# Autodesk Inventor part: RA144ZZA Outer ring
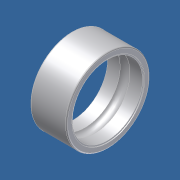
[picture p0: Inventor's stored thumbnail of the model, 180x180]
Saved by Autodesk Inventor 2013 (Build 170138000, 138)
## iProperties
Category: PARTsolutions
Created: 2011-07
Part Number: RA144ZZA Outer ring
Catalog Web Link: www.cadenas.de
Description: Six types or - Inch system sizes
Document SubType Name: Modeling
Designer: PARTsolutions
Density: 1 g/cm^3
Material: Générique
NB: RA144ZZA Outer ring
NN: Six types or
NT: Inch system sizes
NBSYN: RA144ZZA Outer ring
LINA: RA144ZZA Outer ring
SD: 3.175
D: 6.350
B: 2.380
B1: 2.779
D1: 7.52
D2: 7.52
C1: 0.58
C2: 0.79
R: 0.08
ORDER: RA144ZZA
CR: 284
COR: 96
CRF: 29
CORF: 10
LSG: 59000
LSO: 70000
MASS: 0.27
ORDER1: R144
WSS: RA144ZA
WDS: RA144ZZA
UTWF: FLR144
FORSS: FLRA144ZA
FORDS: FLRA144ZZA
DA1: 3.9
DA2: 4
DA: 5.5
RAS: 0.08
MASS1: 0.33
VERS: 3
X: 1.587
N: 9
O: 14.954
RB: 0.470
KT: DUMMY
SUPPLIER: NTN
ARTICLENO: RA144ZZA Outer ring
BOMINFO: RA144ZZA Outer ring
CREATOR: CADENAS GmbH
PSOL_IDENT_0: {\\10.0.0.251\ps_data\23d-libs\ntn\ball_roller_bearings\miniature_extra_small_bb\inch_system_sizes\i
PSOL_IDENT_1: ss_or.prj},189 {VTYP=3D},{NB=RA144ZZA Outer ring},{LINA=RA144ZZA Outer ring},{NN=Six types or},{DATE
PSOL_IDENT_2: =11.12.2007 08:48:22},{GEOMDATE=08.02.2007 08:30:00},{VERSION=},{LINEID=16080},{LINESUBID=-1},{WBVAR
PSOL_IDENT_3: =}  {NB=RA144ZZA Outer ring},{LINA=RA144ZZA Outer ring},{KT=DUMMY},{IDNR=},{SD=3.175},{D=6.350},{B=2
PSOL_IDENT_4: .380},{B1=2.779},{D1=7.52},{D2=7.52},{C1=0.58},{C2=0.79},{R=0.08},{ORDER=RA144ZZA},{CR=284},{COR=96}
PSOL_IDENT_5: ,{CRF=29},{CORF=10},{LSG=59000},{LSO=70000},{MASS=0.27},{ORDER1=R144},{WSS=RA144ZA},{WDS=RA144ZZA},{
PSOL_IDENT_6: UTWF=FLR144},{FORSS=FLRA144ZA},{FORDS=FLRA144ZZA},{DA1=3.9},{DA2=4},{DA=5.5},{RAS=0.08},{MASS1=0.33}
PSOL_IDENT_7: ,{VERS=3},{X=1.5875},{N=9},{O=14.95425},{RB=0.4699}
Title: RA144ZZA Outer ring
Author: Cadenas PARTsolutions
Comments: Inch system sizes
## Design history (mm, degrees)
sketch "Sketch_3"
  geometry: L1 (2.779, 0)-(0, 0); L2 (0, 3.095)-(0, 2.769); L3 (0, 2.769)-(0.063, 2.769); L4 (0.063, 2.769)-(0.063, 2.667); L5 (0.063, 2.667)-(1.016, 2.667); L6 (1.763, 2.667)-(2.716, 2.667); L7 (2.716, 2.667)-(2.716, 2.769); L8 (2.716, 2.769)-(2.779, 2.769); L9 (2.779, 2.769)-(2.779, 3.095); L10 (2.699, 3.175)-(0.08, 3.175); A1 r 0.47 centre (1.39, 2.381) between (1.763, 2.667) and (1.016, 2.667); A2 r 0.08 centre (2.699, 3.095) between (2.779, 3.095) and (2.699, 3.175); A3 r 0.08 centre (0.08, 3.095) between (0.08, 3.175) and (0, 3.095)
  constraints: 20 end point, 6 point on circle, 3 centre point
revolve "Revolution1" sketch "Sketch_3" stored, may be unused: angle "d0" = 360 deg
node "iss_or_XY"
node "iss_or_YZ"
node "iss_or_ZX"
node "iss_or_X"
node "iss_or_Y"
node "iss_or_Z"
node "iss_or_Center"
node "iss_or11_XY"
node "iss_or11_YZ"
node "iss_or11_ZX"
node "iss_or11_X"
node "iss_or11_Y"
node "iss_or11_Z"
node "iss_or11_Center"
node "iss_or2_9_XY"
node "iss_or2_9_YZ"
node "iss_or2_9_ZX"
node "iss_or2_9_X"
node "iss_or2_9_Y"
node "iss_or2_9_Z"
node "iss_or2_9_Center"
node "iss_or2_8_XY"
node "iss_or2_8_YZ"
node "iss_or2_8_ZX"
node "iss_or2_8_X"
node "iss_or2_8_Y"
node "iss_or2_8_Z"
node "iss_or2_8_Center"
node "iss_or2_1_XY"
node "iss_or2_1_YZ"
node "iss_or2_1_ZX"
node "iss_or2_1_X"
node "iss_or2_1_Y"
node "iss_or2_1_Z"
node "iss_or2_1_Center"
node "iss_or2_3_XY"
node "iss_or2_3_YZ"
node "iss_or2_3_ZX"
node "iss_or2_3_X"
node "iss_or2_3_Y"
node "iss_or2_3_Z"
node "iss_or2_3_Center"
node "iss_or2_2_XY"
node "iss_or2_2_YZ"
node "iss_or2_2_ZX"
node "iss_or2_2_X"
node "iss_or2_2_Y"
node "iss_or2_2_Z"
node "iss_or2_2_Center"
node "iss_or2_5_XY"
node "iss_or2_5_YZ"
node "iss_or2_5_ZX"
node "iss_or2_5_X"
node "iss_or2_5_Y"
node "iss_or2_5_Z"
node "iss_or2_5_Center"
node "iss_or2_4_XY"
node "iss_or2_4_YZ"
node "iss_or2_4_ZX"
node "iss_or2_4_X"
node "iss_or2_4_Y"
node "iss_or2_4_Z"
node "iss_or2_4_Center"
node "iss_or2_7_XY"
node "iss_or2_7_YZ"
node "iss_or2_7_ZX"
node "iss_or2_7_X"
node "iss_or2_7_Y"
node "iss_or2_7_Z"
node "iss_or2_7_Center"
node "iss_or2_6_XY"
node "iss_or2_6_YZ"
node "iss_or2_6_ZX"
node "iss_or2_6_X"
node "iss_or2_6_Y"
node "iss_or2_6_Z"
node "iss_or2_6_Center"
node "iss_or21_9_XY"
node "iss_or21_9_YZ"
node "iss_or21_9_ZX"
node "iss_or21_9_X"
node "iss_or21_9_Y"
node "iss_or21_9_Z"
node "iss_or21_9_Center"
node "iss_or21_8_XY"
node "iss_or21_8_YZ"
node "iss_or21_8_ZX"
node "iss_or21_8_X"
node "iss_or21_8_Y"
node "iss_or21_8_Z"
node "iss_or21_8_Center"
node "iss_or21_3_XY"
node "iss_or21_3_YZ"
node "iss_or21_3_ZX"
node "iss_or21_3_X"
node "iss_or21_3_Y"
node "iss_or21_3_Z"
node "iss_or21_3_Center"
node "iss_or21_2_XY"
node "iss_or21_2_YZ"
node "iss_or21_2_ZX"
node "iss_or21_2_X"
node "iss_or21_2_Y"
node "iss_or21_2_Z"
node "iss_or21_2_Center"
node "iss_or21_1_XY"
node "iss_or21_1_YZ"
node "iss_or21_1_ZX"
node "iss_or21_1_X"
node "iss_or21_1_Y"
node "iss_or21_1_Z"
node "iss_or21_1_Center"
node "iss_or21_7_XY"
node "iss_or21_7_YZ"
node "iss_or21_7_ZX"
node "iss_or21_7_X"
node "iss_or21_7_Y"
node "iss_or21_7_Z"
node "iss_or21_7_Center"
node "iss_or21_6_XY"
node "iss_or21_6_YZ"
node "iss_or21_6_ZX"
node "iss_or21_6_X"
node "iss_or21_6_Y"
node "iss_or21_6_Z"
node "iss_or21_6_Center"
node "iss_or21_5_XY"
node "iss_or21_5_YZ"
node "iss_or21_5_ZX"
node "iss_or21_5_X"
node "iss_or21_5_Y"
node "iss_or21_5_Z"
node "iss_or21_5_Center"
node "iss_or21_4_XY"
node "iss_or21_4_YZ"
node "iss_or21_4_ZX"
node "iss_or21_4_X"
node "iss_or21_4_Y"
node "iss_or21_4_Z"
node "iss_or21_4_Center"
node "Solide1"
node "Corps solides"
node "Corps surfaciques"
